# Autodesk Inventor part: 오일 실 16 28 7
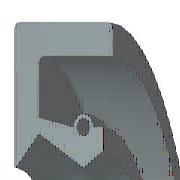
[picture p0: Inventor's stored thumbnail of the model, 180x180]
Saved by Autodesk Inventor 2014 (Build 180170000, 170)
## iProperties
Created: 2012-02
Part Number: 오일 실 16 28 7
Material: 고무
Description: 오일-실
Document SubType Name: Modeling
Standard: KS B 2804
Designer: mduedu
Standards Organization: KS
Language: ko-KR
Size Designation: D - 16 28 7
Categories: <MemberInstance><Categories><Category DisplayName="샤프트 부품" InternalName="7f7aeb1f-a693-4053-b835-cee3144e0d98" Mnemonic="SHFT"><Category DisplayName="실링" Intern
Density: 0.93 g/cm^3
Appearance: 고무 - 검은색 - 버전 1.1
IsCustomPart: 1
Author: mduedu
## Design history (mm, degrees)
revolve "본체" stored, may be unused: angle "d17" = 90 deg
revolve "스프링1" stored, may be unused: angle "d18" = 90 deg
fillet "모깎기3" dims "d43" = 0.5
body "Solid1"
sketch "스케치1"
  geometry: L1 (0, 14)-(7, 14); L2 (7, 12.25)-(1.75, 12.25); L3 (1.75, 9.75)-(4.9, 8); L4 (4.9, 8)-(0, 8); L5 (0, 0)-(9.586, 0) reference; L6 (4.9, 8)-(6.3, 8.875); L7 (0, 18)-(0, -3) reference; L8 (-1.941, 0)-(11.507, 0) reference; L9 (4.2, 10.1)-(1.75, 10.59); L10 (1.75, 10.59)-(1.75, 12.25); L11 (0, 14)-(0, 8.088); L12 (4.9, 8)-(0, 8); L13 (1.75, 9.75)-(0.152, 8.028); L14 (7, 14)-(7, 12.25); L15 (5.6, 10.1)-(6.3, 10.1); L16 (6.3, 10.1)-(6.3, 8.875); C1 r 0.455 at (4.9, 10.1); A1 r 0.7 centre (4.9, 10.1) between (5.6, 10.1) and (4.2, 10.1); A2 r 0.088 centre (0.088, 8.088) between (0, 8.088) and (0.152, 8.028); 1 further point
  constraints: 28 end point, 5 horizontal alignment, 5 point on line, 4 point on circle, 4 vertical alignment, 3 centre point, 3 tangent, 2 collinear, 2 horizontal, 2 perpendicular, 1 coincident, 1 parallel
  dimensions: "d0" = 28 diameter of L1 L5 (= SD2); "d1" = 1.75 distance of L1.end L2.start (= SD); "d2" = 0.91 diameter of C1 (= SPDI); "d3" = 1.4 diameter of A1 (= SPDA); "d4" = 16 diameter of L3.end L5 (= NND); "d5" = 19.5 diameter of L3.start L5 (= TKDM); "d7" = 21.18 diameter of L9.end L5 (= TKDM + 0.24 x SWDT); "d8" = 1.75 distance between parallel lines of L11 L10 (= SD); "d9" = 4.9 distance from line of L11 C1.centre (= SPDST); "d10" = 20.2 diameter of C1.centre L5 (= HLDM); "d11" = 0.0875 radius of A2 (= 0.25 x LAB); "d12" = 6.3 distance between parallel lines of L11 L16 (= SDI); "d13" = 17.75 diameter of L6.end L5 (= ABDM); "d14" = 7 distance from line of L11 L1.end (= SWDT)
fillet "모깎기1" dims "d6" = 0.3 (= RR)
other parameters: "SD2" = 28 [user parameter; used in 1 equation term], "SWDT" = 7 [user parameter; used in 2 equation terms], "RR" = 0.3 [user parameter; used in 1 equation term], "SD" = 1.75 [user parameter; used in 2 equation terms], "NND" = 16 [user parameter; used in 1 equation term], "SPDA" = 1.4 [user parameter; used in 1 equation term], "SPDI" = 0.91 [user parameter; used in 1 equation term], "TKDM" = 19.5 [user parameter; used in 2 equation terms], "HLDM" = 20.2 [user parameter; used in 1 equation term], "ABDM" = 17.75 [user parameter; used in 1 equation term], "SDI" = 6.3 [user parameter; used in 1 equation term], "SPDST" = 4.9 [user parameter; used in 1 equation term], "LAB" = 0.35 [user parameter; used in 1 equation term], "d15" = 0, "d16" = 0, "d19" = 0
